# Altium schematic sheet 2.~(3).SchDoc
size 420 x 297 mm
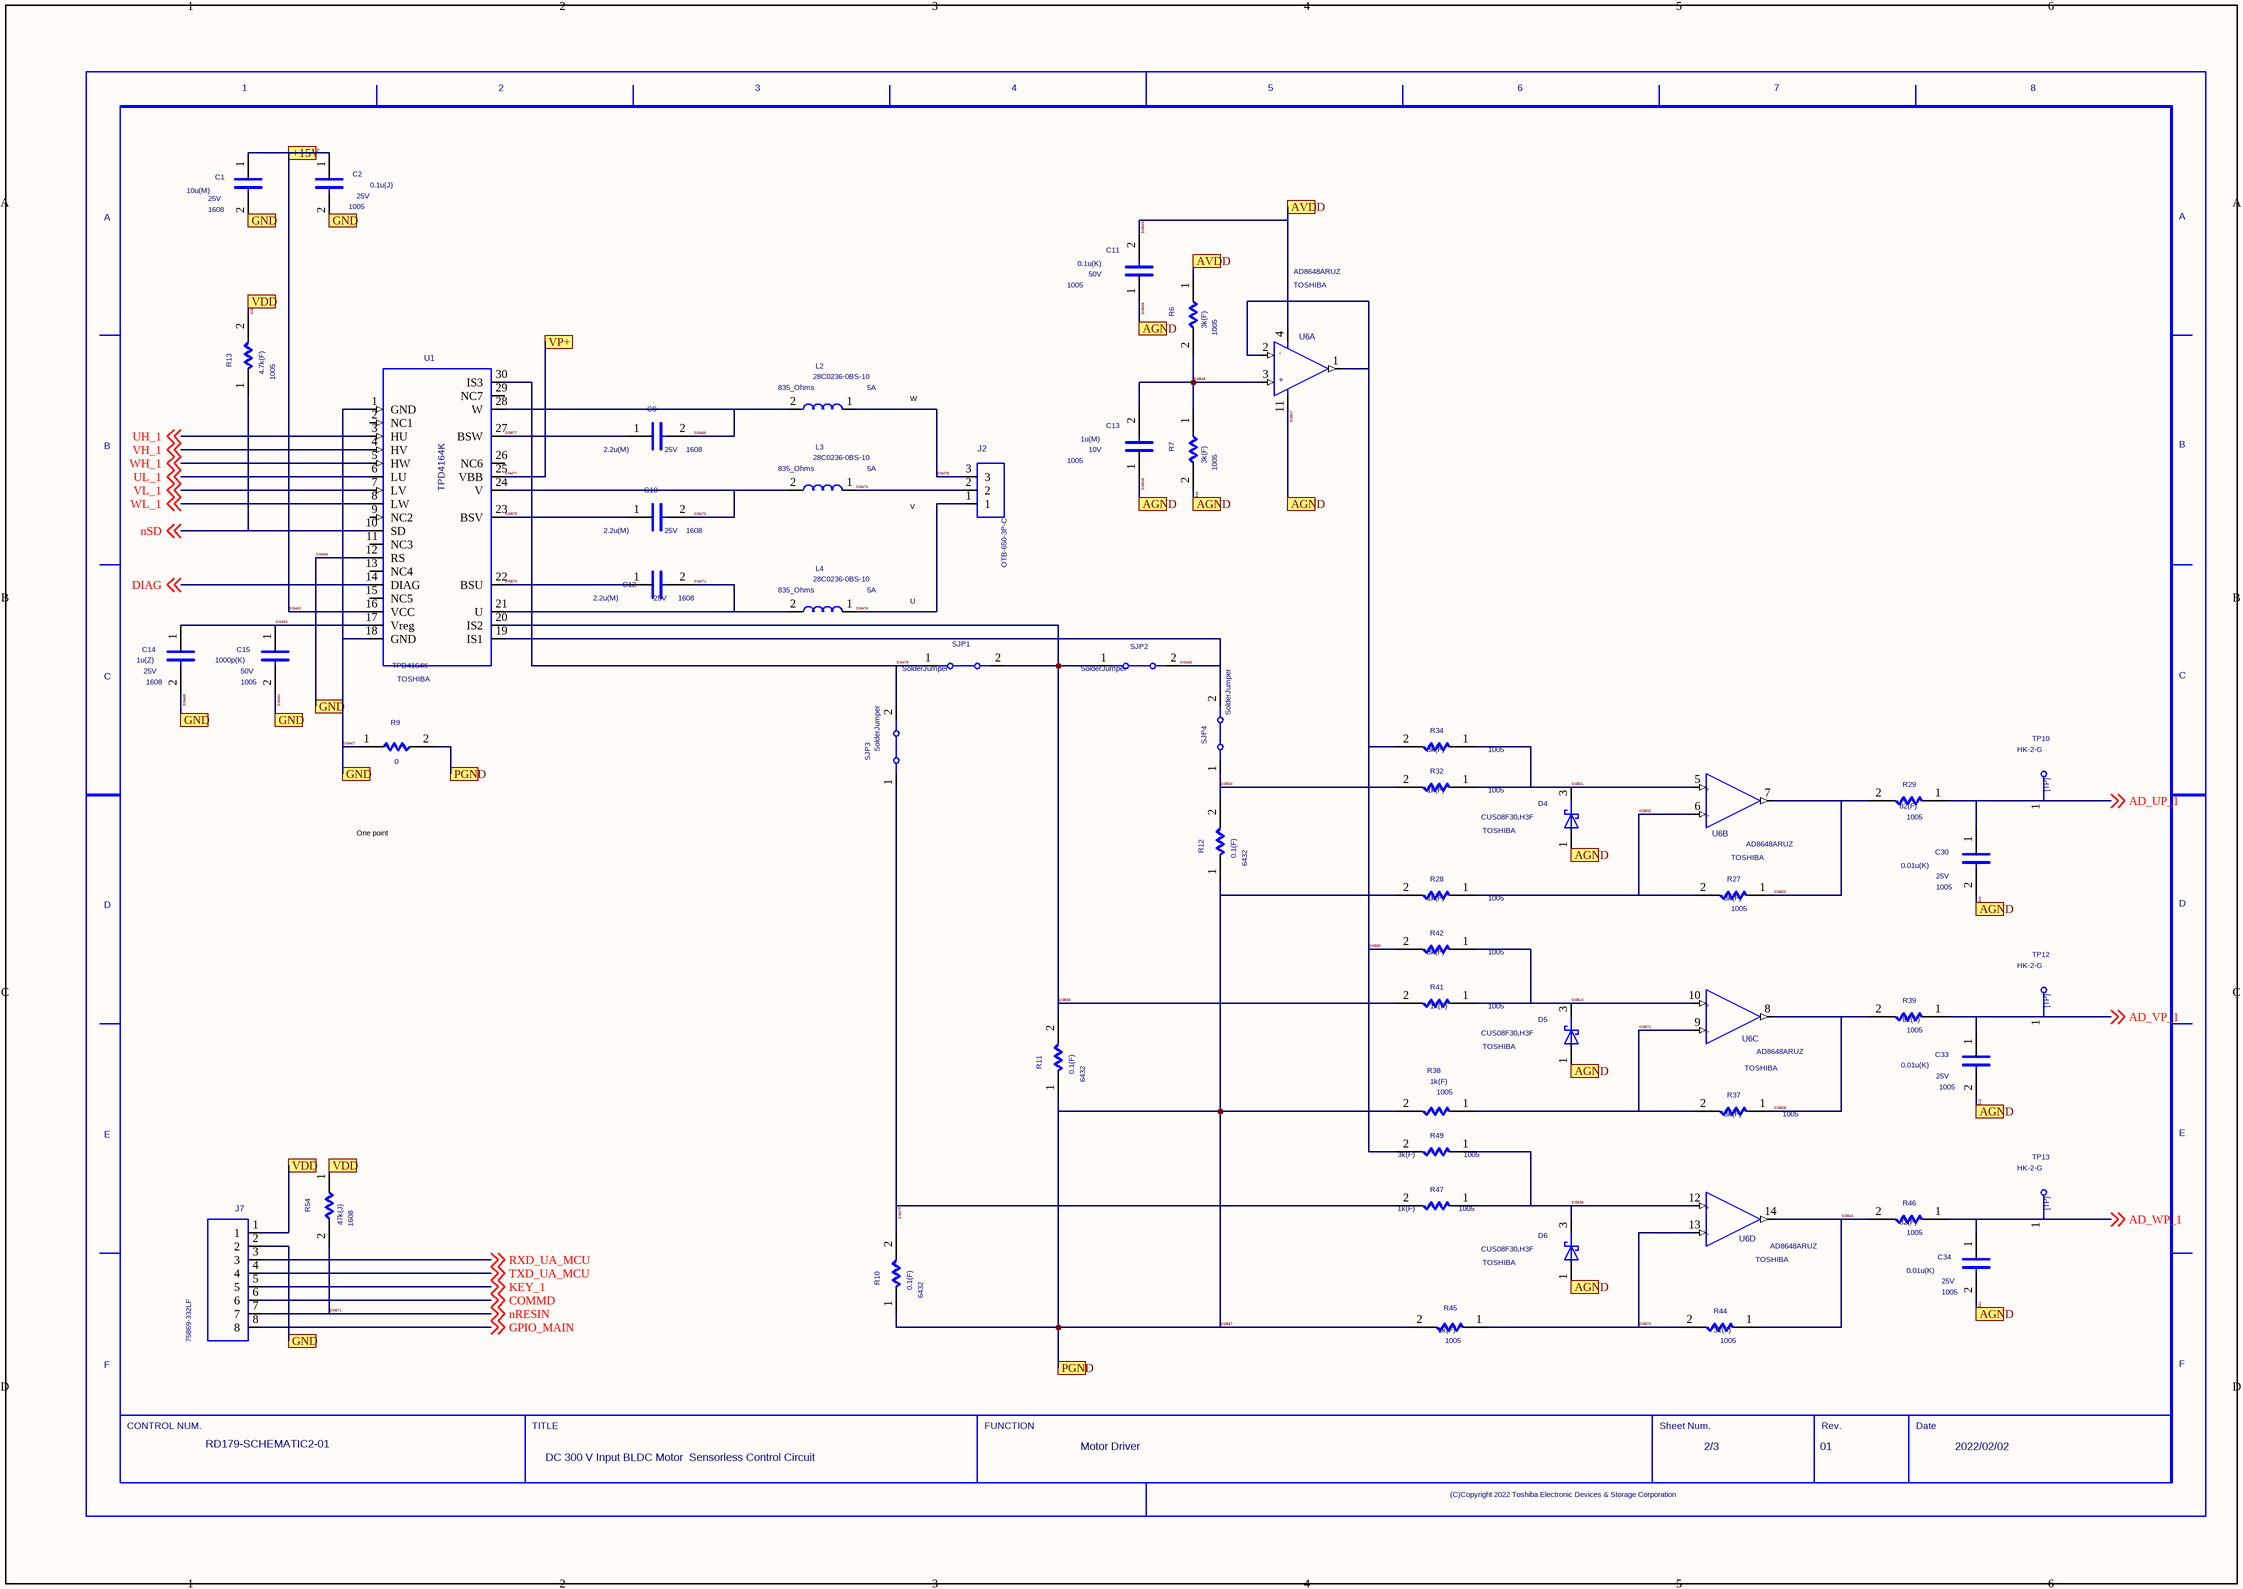
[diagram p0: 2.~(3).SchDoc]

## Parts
C1  SIZECODESMD: 1608  VAL2: 25V  VAL1: 10u(M)  (hidden comment: C)
C2  SIZECODESMD: 1005  VAL2: 25V  VAL1: 0.1u(J)  (hidden comment: C)
C9  SIZECODESMD: 1608  VAL2: 25V  VAL1: 2.2u(M)  (hidden comment: C)
C10  SIZECODESMD: 1608  VAL2: 25V  VAL1: 2.2u(M)  (hidden comment: C)
C11  SIZECODESMD: 1005  VAL2: 50V  VAL1: 0.1u(K)  (hidden comment: C)
C12  SIZECODESMD: 1608  VAL2: 25V  VAL1: 2.2u(M)  (hidden comment: C)
C13  SIZECODESMD: 1005  VAL2: 10V  VAL1: 1u(M)  (hidden comment: C)
C14  SIZECODESMD: 1608  VAL2: 25V  VAL1: 1u(Z)  (hidden comment: C)
C15  SIZECODESMD: 1005  VAL2: 50V  VAL1: 1000p(K)  (hidden comment: C)
C30  SIZECODESMD: 1005  VAL2: 25V  VAL1: 0.01u(K)  (hidden comment: C)
C33  SIZECODESMD: 1005  VAL2: 25V  VAL1: 0.01u(K)  (hidden comment: C)
C34  SIZECODESMD: 1005  VAL2: 25V  VAL1: 0.01u(K)  (hidden comment: C)
D4  USERCOMPTEXT3: TOSHIBA  VAL3: CUS08F30,H3F  (hidden comment: SBD)
D5  USERCOMPTEXT3: TOSHIBA  VAL3: CUS08F30,H3F  (hidden comment: SBD)
D6  USERCOMPTEXT3: TOSHIBA  VAL3: CUS08F30,H3F  (hidden comment: SBD)
J2  OTB-650-3P-C
J7  75869-332LF
L2  VAL3: 28C0236-0BS-10  VAL2: 5A  VAL1: 835_Ohms  (hidden comment: L)
L3  VAL3: 28C0236-0BS-10  VAL2: 5A  VAL1: 835_Ohms  (hidden comment: L)
L4  VAL3: 28C0236-0BS-10  VAL2: 5A  VAL1: 835_Ohms  (hidden comment: L)
R6  SIZECODESMD: 1005  VAL1: 3k(F)  (hidden comment: R)
R7  SIZECODESMD: 1005  VAL1: 3k(F)  (hidden comment: R)
R9  VAL1: 0  (hidden comment: R)
R10  SIZECODESMD: 6432  VAL1: 0.1(F)  (hidden comment: R)
R11  SIZECODESMD: 6432  VAL1: 0.1(F)  (hidden comment: R)
R12  SIZECODESMD: 6432  VAL1: 0.1(F)  (hidden comment: R)
R13  SIZECODESMD: 1005  VAL1: 4.7k(F)  (hidden comment: R)
R27  SIZECODESMD: 1005  VAL1: 3k(F)  (hidden comment: R)
R28  SIZECODESMD: 1005  VAL1: 1k(F)  (hidden comment: R)
R29  SIZECODESMD: 1005  VAL1: 82(F)  (hidden comment: R)
R32  SIZECODESMD: 1005  VAL1: 1k(F)  (hidden comment: R)
R34  SIZECODESMD: 1005  VAL1: 3k(F)  (hidden comment: R)
R37  SIZECODESMD: 1005  VAL1: 3k(F)  (hidden comment: R)
R38  SIZECODESMD: 1005  VAL1: 1k(F)  (hidden comment: R)
R39  SIZECODESMD: 1005  VAL1: 82(F)  (hidden comment: R)
R41  SIZECODESMD: 1005  VAL1: 1k(F)  (hidden comment: R)
R42  SIZECODESMD: 1005  VAL1: 3k(F)  (hidden comment: R)
R44  SIZECODESMD: 1005  VAL1: 3k(F)  (hidden comment: R)
R45  SIZECODESMD: 1005  VAL1: 1k(F)  (hidden comment: R)
R46  SIZECODESMD: 1005  VAL1: 82(F)  (hidden comment: R)
R47  SIZECODESMD: 1005  VAL1: 1k(F)  (hidden comment: R)
R49  SIZECODESMD: 1005  VAL1: 3k(F)  (hidden comment: R)
R54  SIZECODESMD: 1608  VAL1: 47k(J)  (hidden comment: R)
SJP1  VAL3: SolderJumper  (hidden comment: JP)
SJP2  VAL3: SolderJumper  (hidden comment: JP)
SJP3  VAL3: SolderJumper  (hidden comment: JP)
SJP4  VAL3: SolderJumper  (hidden comment: JP)
TP10  VAL3: HK-2-G  (hidden comment: TP)
TP12  VAL3: HK-2-G  (hidden comment: TP)
TP13  VAL3: HK-2-G  (hidden comment: TP)
U1  USERCOMPTEXT3: TOSHIBA  (hidden comment: TPD4164K)
U6  USERCOMPTEXT3: TOSHIBA  VAL3: AD8648ARUZ  (hidden comment: AD8648ARUZ_1)  (parts A,B,C,D of 4)
U?  DATE: 2022/02/02  TITLE: DC 300 V Input BLDC Motor / Sensorless Control Circuit  FUNCTION: Motor Driver  REVISION: 01  SHEETNUMBER: 2/3  DRAWINGNUMBER: RD179-SCHEMATIC2-01  (hidden comment: WAKU_DEF100)

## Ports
+15V, AGND, AVDD, GND, PGND, VDD, VP+

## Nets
AD_UP_1: C30.1 R29.1 TP10.1 ; off-sheet AD_UP_1
AD_VP_1: C33.1 R39.1 TP12.1 ; off-sheet AD_VP_1
AD_WP_1: C34.1 R46.1 TP13.1 ; off-sheet AD_WP_1
COMMD: J7.6 ; off-sheet COMMD
DIAG: U1.14(DIAG) ; off-sheet DIAG
GPIO_MAIN: J7.8 ; off-sheet GPIO_MAIN
KEY_1: J7.5 ; off-sheet KEY_1
nSD: R13.1 U1.10(SD) ; off-sheet nSD
RXD_UA_MCU: J7.3 ; off-sheet RXD_UA_MCU
SIG454: J7.1 R13.2 R54.1 ; port VDD
SIG462: C1.1 C2.1 U1.16(VCC) ; port +15V
SIG463: C14.1 C15.1 U1.17(Vreg)
SIG464: C1.2 C2.2 C14.2 C15.2 J7.2 R9.1 U1.1(GND) U1.12(RS) U1.18(GND) ; port GND  [also labelled SIG465, SIG466, SIG467]
SIG469: C9.2 L2.2 U1.28(W)
SIG471: C12.2 L4.2 U1.21(U)
SIG473: C10.2 L3.2 U1.24(V)
SIG474: J2.2 L3.1
SIG475: J2.3 L2.1
SIG476: J2.1 L4.1
SIG477: U1.25(VBB) ; port VP+
SIG478: SJP1.1 SJP3.2 U1.30(IS3)
SIG479: R10.2 R47.2 SJP3.1
SIG480: SJP2.2 SJP4.2 U1.19(IS1)
SIG500: R12.2 R32.2 SJP4.1
SIG501: D4.3(C) R32.1 R34.1 U6.5
SIG502: R27.2 R28.1 U6.6
SIG503: R27.1 R29.2 U6.7
SIG504: C11.1 C13.1 C30.2 C33.2 C34.2 D4.1(A) D5.1(A) D6.1(A) R7.2 U6.11(GND) ; port AGND  [also labelled SIG512, SIG541, SIG544, SIG545, SIG547, SIG548]
SIG508: R37.1 R39.2 U6.8
SIG510: D5.3(C) R41.1 R42.1 U6.10
SIG538: D6.3(C) R47.1 R49.1 U6.12
SIG542: R44.1 R46.2 U6.14
SIG546: C13.2 R6.2 R7.1 U6.3(IN+)
SIG549: C11.2 R6.1 U6.4(VCC) ; port AVDD
SIG550: R34.2 R42.2 R49.2 U6.1(OUT) U6.2(IN-)
SIG567: R9.2 R10.1 R11.1 R12.1 R28.2 R38.2 R45.2 ; port PGND
SIG568: R11.2 R41.2 SJP1.2 SJP2.1 U1.20(IS2)
SIG571: J7.7 R54.2 ; off-sheet nRESIN  [also labelled nRESIN]
SIG573: R44.2 R45.1 U6.13
SIG574: R37.2 R38.1 U6.9
SIG577: C9.1 U1.27(BSW)
SIG578: C10.1 U1.23(BSV)
SIG579: C12.1 U1.22(BSU)
TXD_UA_MCU: J7.4 ; off-sheet TXD_UA_MCU
UH_1: U1.3(HU) ; off-sheet UH_1
UL_1: U1.6(LU) ; off-sheet UL_1
VH_1: U1.4(HV) ; off-sheet VH_1
VL_1: U1.7(LV) ; off-sheet VL_1
WH_1: U1.5(HW) ; off-sheet WH_1
WL_1: U1.8(LW) ; off-sheet WL_1

Not connected (* = marked no-connect by the designer): U1 2(NC1) 9(NC2) 11(NC3) 13(NC4) 15(NC5) 26(NC6) 29(NC7)

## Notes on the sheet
- W
- V
- U
- One point
  ground

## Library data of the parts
C1 C9 C10 C12 C14 = C: OriginalSymbolOrigin: (2540,7620); COMP: CRC-1608-DEF
C2 C11 C13 C15 C30 C33 C34 = C: OriginalSymbolOrigin: (2540,7620); COMP: CRC-1005-DEF
D4-D6 = SBD: SAVEAREA0: -4630,-153,17114,13055; TIME: 14:49:55; UPDATEUSER: fukuda-y; UPDATETIME: 08:16:22; SAVECOUNT: 9; OriginalSymbolOrigin: (5080,5080); COMP: CD-USC-05
J2 = OTB_650_3P_C: COMP: OTB-650-3P_R00; TIME: 16:31:59; UPDATEUSER: t5459927; SAVECOUNT: 1; SAVEAREA0: -6361,-10384,8548,546; OriginalSymbolOrigin: (0,0); INSTANCENAME: I541179
J7 = CON8: COMP: 75869-332LF_R00; ORDER: 0; TIME: 16:31:59; UPDATEUSER: t5459927; SAVECOUNT: 1; SAVEAREA0: -14610,-23317,18939,1279; OriginalSymbolOrigin: (0,0); INSTANCENAME: I16797633
L2-L4 = L: OriginalSymbolOrigin: (2540,5080); COMP: DL-1460-01
R6 R7 R27 R28 R32 R34 R37 R38 R41 R42 R44 R45 R47 R49 = R: OriginalSymbolOrigin: (5080,5080); VAL2: 100mW; COMP: CRC-1005-DEF
R9 = R: OriginalSymbolOrigin: (5080,5080); COMP: CX-0002-75
R10-R12 = R: OriginalSymbolOrigin: (5080,5080); VAL2: 3W; COMP: CR-6432-18
R13 R29 R39 R46 = R: OriginalSymbolOrigin: (5080,5080); VAL2: 63mW; COMP: CRC-1005-DEF
R54 = R: OriginalSymbolOrigin: (5080,5080); VAL2: 100mW; COMP: CRC-1608-DEF
SJP1-SJP4 = JP: OriginalSymbolOrigin: (2540,5080); COMP: CJP-0002-116
TP10 TP12 TP13 = TP: TIME: 16:12:21; UPDATEUSER: fukuda-y; UPDATETIME: 16:18:11; SAVECOUNT: 2; SAVEAREA0: -242,-92,12810,7836; OriginalSymbolOrigin: (0,7620)
U1 = TPD4164K: TIME: 16:32:01; UPDATEUSER: t5459927; UPDATETIME: 10:27:03; SAVECOUNT: 9; SAVEAREA0: -62008,-64713,81811,-4545; OriginalSymbolOrigin: (0,0)
U6 = AD8648ARUZ_1: TIME: 16:31:59; UPDATEUSER: t5459927; UPDATETIME: 15:23:55; SAVECOUNT: 10; OriginalSymbolOrigin: (0,0); SAVEAREA0: -20143,-23389,30103,13502; CaptureCellPackProp: AD8648ARUZ_1A
U? = WAKU_DEF100: PLOTTIME: HH:MM; SAVEAREA0: 147884,-66467,487065,89883; TIME: 14:30:25; UPDATEUSER: t5459927; UPDATETIME: 12:52:19; SAVECOUNT: 7; OriginalSymbolOrigin: (10160,284480)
